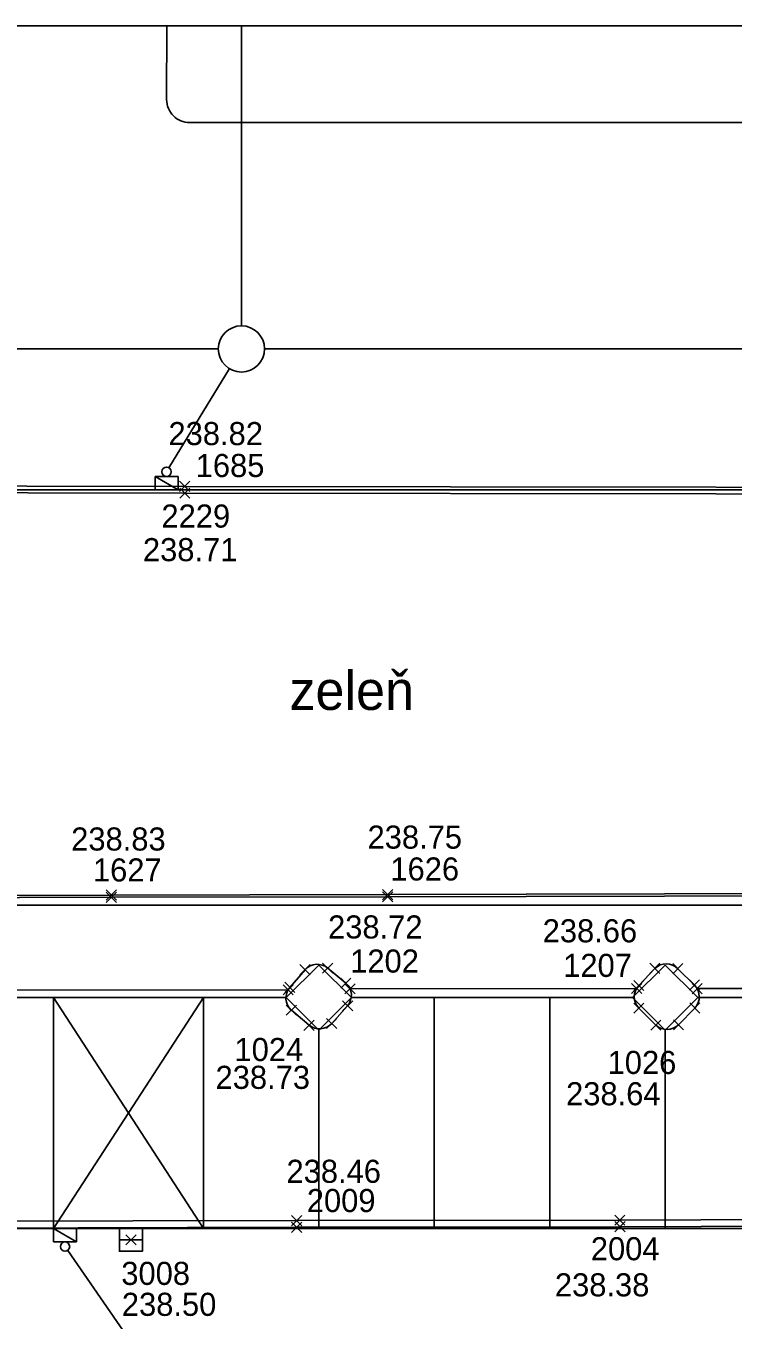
# Model space of a CAD drawing. Extents: x -264165 to -263733, y -1242319 to -1242245.
# Drawn here: x -263956.67 to -263941.36, y -1242272.97 to -1242244.94 of the extents above; entities that cross this region are included whole.
import ezdxf

# ---------------------------------------------------------------- set-up
doc = ezdxf.new("R2010")
doc.units = 0
for name, color, linetype in [('KFA_BOD_CISLO', 7, 'Continuous'), ('KFA_BOD_SYMBOL', 7, 'Continuous'), ('KFA_BOD_VYSKA', 7, 'Continuous'), ('KFA_SO_20-2_OBRUBNIKY_DOLNA_HRANA', 7, 'Continuous'), ('KFA_SO_20-2_OBRUBNIKY_HORNA_HRANA', 7, 'Continuous'), ('KFA_UV_BOD_CISLO', 7, 'Continuous'), ('KFA_UV_BOD_SYMBOL', 7, 'Continuous'), ('KFA_UV_BOD_VYSKA', 7, 'Continuous'), ('POPIS', 7, 'Continuous'), ('PROJEKT_OBRUBNIKY_KOMUNIKACIE', 7, 'Continuous'), ('PROJEKT_TDZ_VODOROVNE', 7, 'Continuous'), ('RAM_NA_TLAC_1-250', 7, 'Continuous'), ('SITUACIA_DSP_2D', 7, 'Continuous'), ('ULICNA_VPUST_POKLOP', 7, 'Continuous')]:
    doc.layers.add(name, color=color, linetype=linetype)

msp = doc.modelspace()

# ---------------------------------------------------------------- linework, layer by layer
at = {"layer": 'KFA_BOD_SYMBOL'}
for p, q in [((-263953.338, -1242255.021), (-263953.117, -1242254.799)), ((-263953.117, -1242255.021), (-263953.338, -1242254.799)), ((-263953.334, -1242255.164), (-263953.113, -1242254.944)), ((-263953.113, -1242255.164), (-263953.334, -1242254.944)), ((-263954.927, -1242263.87), (-263954.705, -1242263.649)), ((-263954.705, -1242263.87), (-263954.927, -1242263.649)), ((-263954.927, -1242263.92), (-263954.705, -1242263.698)), ((-263954.705, -1242263.92), (-263954.927, -1242263.698)), ((-263948.943, -1242263.86), (-263948.721, -1242263.639)), ((-263948.721, -1242263.86), (-263948.943, -1242263.639)), ((-263948.943, -1242263.91), (-263948.721, -1242263.688)), ((-263948.721, -1242263.91), (-263948.943, -1242263.688)), ((-263950.734, -1242265.487), (-263950.513, -1242265.265)), ((-263950.513, -1242265.487), (-263950.734, -1242265.265)), ((-263950.242, -1242265.454), (-263950.02, -1242265.232)), ((-263950.02, -1242265.454), (-263950.242, -1242265.232)), ((-263943.161, -1242265.458), (-263942.94, -1242265.238)), ((-263942.94, -1242265.458), (-263943.161, -1242265.238)), ((-263942.663, -1242265.465), (-263942.442, -1242265.245)), ((-263942.442, -1242265.465), (-263942.663, -1242265.245)), ((-263951.099, -1242265.923), (-263950.878, -1242265.701)), ((-263950.878, -1242265.923), (-263951.099, -1242265.701)), ((-263951.062, -1242265.872), (-263950.84, -1242265.65)), ((-263950.84, -1242265.872), (-263951.062, -1242265.65)), ((-263949.85, -1242265.779), (-263949.628, -1242265.558)), ((-263949.628, -1242265.779), (-263949.85, -1242265.558)), ((-263949.759, -1242265.901), (-263949.538, -1242265.681)), ((-263949.538, -1242265.901), (-263949.759, -1242265.681)), ((-263943.555, -1242265.894), (-263943.334, -1242265.674)), ((-263943.334, -1242265.894), (-263943.555, -1242265.674)), ((-263943.506, -1242265.83), (-263943.285, -1242265.61)), ((-263943.285, -1242265.83), (-263943.506, -1242265.61)), ((-263942.302, -1242265.819), (-263942.081, -1242265.599)), ((-263942.081, -1242265.819), (-263942.302, -1242265.599)), ((-263942.243, -1242265.897), (-263942.022, -1242265.677)), ((-263942.022, -1242265.897), (-263942.243, -1242265.677)), ((-263949.812, -1242266.269), (-263949.59, -1242266.048)), ((-263949.59, -1242266.269), (-263949.812, -1242266.048)), ((-263951.03, -1242266.365), (-263950.808, -1242266.144)), ((-263950.808, -1242266.365), (-263951.03, -1242266.144)), ((-263943.507, -1242266.32), (-263943.285, -1242266.1)), ((-263943.285, -1242266.32), (-263943.507, -1242266.1)), ((-263942.295, -1242266.318), (-263942.073, -1242266.096)), ((-263942.073, -1242266.318), (-263942.295, -1242266.096)), ((-263950.647, -1242266.69), (-263950.426, -1242266.468)), ((-263950.426, -1242266.69), (-263950.647, -1242266.468)), ((-263950.155, -1242266.65), (-263949.933, -1242266.43)), ((-263949.933, -1242266.65), (-263950.155, -1242266.43)), ((-263943.139, -1242266.688), (-263942.917, -1242266.467)), ((-263942.917, -1242266.688), (-263943.139, -1242266.467)), ((-263942.649, -1242266.681), (-263942.428, -1242266.46)), ((-263942.428, -1242266.681), (-263942.649, -1242266.46)), ((-263950.916, -1242270.921), (-263950.695, -1242270.701)), ((-263950.695, -1242270.921), (-263950.916, -1242270.701)), ((-263943.919, -1242270.911), (-263943.698, -1242270.691)), ((-263943.698, -1242270.911), (-263943.919, -1242270.691)), ((-263950.915, -1242271.066), (-263950.693, -1242270.846)), ((-263950.693, -1242271.066), (-263950.915, -1242270.846)), ((-263943.914, -1242271.055), (-263943.693, -1242270.833)), ((-263943.693, -1242271.055), (-263943.914, -1242270.833))]:
    msp.add_line(p, q, dxfattribs=at)
at = {"layer": 'KFA_SO_20-2_OBRUBNIKY_DOLNA_HRANA'}
for points in [[(-263970.225, -1242255.029), (-263963.43, -1242255.035), (-263953.224, -1242255.054), (-263930.231, -1242255.088)], [(-263965.289, -1242270.846), (-263957.9, -1242270.825), (-263950.806, -1242270.811), (-263943.808, -1242270.801), (-263936.795, -1242270.772), (-263929.578, -1242270.752)], [(-263965.143, -1242270.987), (-263957.899, -1242270.977), (-263950.804, -1242270.956), (-263943.803, -1242270.944), (-263936.794, -1242270.917), (-263929.31, -1242270.895)]]:
    msp.add_lwpolyline(points, dxfattribs=at)
at = {"layer": 'KFA_SO_20-2_OBRUBNIKY_HORNA_HRANA'}
for p, q in [((-263950.951, -1242265.761), (-263950.623, -1242265.376)), ((-263950.131, -1242265.343), (-263949.739, -1242265.668)), ((-263943.395, -1242265.72), (-263943.051, -1242265.348)), ((-263942.552, -1242265.355), (-263942.192, -1242265.709)), ((-263942.133, -1242265.787), (-263935.922, -1242265.777)), ((-263957.867, -1242265.823), (-263950.988, -1242265.812)), ((-263949.649, -1242265.791), (-263943.444, -1242265.784)), ((-263950.919, -1242266.254), (-263950.536, -1242266.579)), ((-263949.701, -1242266.158), (-263950.044, -1242266.54)), ((-263943.396, -1242266.21), (-263943.028, -1242266.577)), ((-263942.184, -1242266.207), (-263942.539, -1242266.57))]:
    msp.add_line(p, q, dxfattribs=at)
for points in [[(-263970.225, -1242254.882), (-263963.483, -1242254.892), (-263953.227, -1242254.91), (-263930.229, -1242254.938)], [(-263927.032, -1242263.694), (-263929.858, -1242263.715), (-263931.859, -1242263.708), (-263939.843, -1242263.726), (-263948.832, -1242263.749), (-263954.816, -1242263.759), (-263960.791, -1242263.777), (-263965.254, -1242263.802), (-263965.276, -1242265.854)], [(-263927.18, -1242263.745), (-263929.889, -1242263.765), (-263931.859, -1242263.758), (-263939.843, -1242263.776), (-263948.832, -1242263.799), (-263954.816, -1242263.809), (-263960.791, -1242263.827), (-263965.205, -1242263.852), (-263965.226, -1242265.854)]]:
    msp.add_lwpolyline(points, dxfattribs=at)
for centre, major_axis, ratio, start_param, end_param in [((-263942.805, -1242265.603), (-0.334, -0.118), 0.999583, 3.576129, 5.140228), ((-263950.36, -1242265.609), (-0.344, -0.07), 0.999884, 3.79973, 5.357438), ((-263950.685, -1242265.991), (0.002, -0.352), 0.999397, 3.992341, 5.549094), ((-263949.97, -1242265.932), (0.325, 0.133), 0.999614, 5.197714, 6.746788), ((-263943.139, -1242265.965), (-0.087, -0.344), 0.999684, 4.196564, 5.720294), ((-263942.444, -1242265.962), (0.191, 0.302), 0.999031, 4.520332, 6.062322), ((-263950.31, -1242266.304), (0.29, 0.205), 0.999717, 3.4083, 4.942889), ((-263942.787, -1242266.319), (0.155, 0.317), 0.999622, 2.843241, 4.374597)]:
    msp.add_ellipse(centre, major_axis=major_axis, ratio=ratio, start_param=start_param, end_param=end_param, dxfattribs=at)
at = {"layer": 'KFA_UV_BOD_SYMBOL'}
for p, q in [((-263954.503, -1242271.336), (-263954.281, -1242271.116)), ((-263954.281, -1242271.336), (-263954.503, -1242271.116))]:
    msp.add_line(p, q, dxfattribs=at)
at = {"layer": 'PROJEKT_OBRUBNIKY_KOMUNIKACIE'}
for p, q in [((-263953.618, -1242244.935), (-263953.619, -1242246.529)), ((-263953.119, -1242247.03), (-263930.082, -1242247.03)), ((-263957.861, -1242265.982), (-263951.031, -1242265.982)), ((-263949.617, -1242265.982), (-263943.531, -1242265.982)), ((-263942.117, -1242265.982), (-263936.031, -1242265.982)), ((-263965.568, -1242270.982), (-263929.061, -1242270.982))]:
    msp.add_line(p, q, dxfattribs=at)
for points in [[(-263929.58, -1242254.982), (-263970.077, -1242254.982), (-263970.077, -1242263.982), (-263929.58, -1242263.982), (-263929.58, -1242254.982)], [(-263950.324, -1242265.275), (-263949.617, -1242265.982), (-263950.324, -1242266.689), (-263951.031, -1242265.982), (-263950.324, -1242265.275)], [(-263942.824, -1242265.275), (-263942.117, -1242265.982), (-263942.824, -1242266.689), (-263943.531, -1242265.982), (-263942.824, -1242265.275)]]:
    msp.add_lwpolyline(points, dxfattribs=at)
msp.add_arc((-263953.119, -1242246.53), 0.5, 179.9525, 270, dxfattribs=at)
at = {"layer": 'PROJEKT_TDZ_VODOROVNE'}
for p, q in [((-263956.068, -1242265.982), (-263956.068, -1242270.982)), ((-263956.068, -1242270.982), (-263952.824, -1242265.982)), ((-263956.068, -1242265.982), (-263952.824, -1242270.982)), ((-263952.824, -1242265.982), (-263952.824, -1242270.982)), ((-263947.824, -1242265.982), (-263947.824, -1242270.982)), ((-263945.324, -1242265.982), (-263945.324, -1242270.982)), ((-263950.324, -1242266.689), (-263950.324, -1242270.982)), ((-263942.824, -1242266.689), (-263942.824, -1242270.982))]:
    msp.add_line(p, q, dxfattribs=at)
at = {"layer": 'RAM_NA_TLAC_1-250'}
msp.add_lwpolyline([(-264165.363, -1242244.935), (-263732.863, -1242244.935), (-263732.863, -1242319.185), (-264165.363, -1242319.185)], close=True, dxfattribs=at)
at = {"layer": 'SITUACIA_DSP_2D'}
for p, q in [((-263953.618, -1242244.935), (-263953.619, -1242246.529)), ((-263952, -1242251.432), (-263952, -1242244.935)), ((-263953.119, -1242247.03), (-263930.082, -1242247.03)), ((-263958.575, -1242251.932), (-263952.5, -1242251.932)), ((-263940.302, -1242251.932), (-263951.5, -1242251.932)), ((-263953.57, -1242254.506), (-263952.26, -1242252.359)), ((-263953.87, -1242254.692), (-263953.37, -1242254.692)), ((-263953.87, -1242254.982), (-263953.87, -1242254.692)), ((-263953.87, -1242254.692), (-263953.37, -1242254.982)), ((-263953.87, -1242254.692), (-263953.37, -1242254.982)), ((-263953.37, -1242254.692), (-263953.87, -1242254.692)), ((-263953.37, -1242254.692), (-263953.37, -1242254.982)), ((-263953.37, -1242254.982), (-263953.37, -1242254.692)), ((-263953.37, -1242254.982), (-263953.87, -1242254.982)), ((-263956.068, -1242270.982), (-263955.568, -1242270.982)), ((-263956.068, -1242271.272), (-263956.068, -1242270.982)), ((-263956.068, -1242270.982), (-263955.568, -1242271.272)), ((-263956.068, -1242270.982), (-263955.568, -1242271.272)), ((-263955.568, -1242270.982), (-263956.068, -1242270.982)), ((-263955.568, -1242270.982), (-263955.568, -1242271.272)), ((-263955.568, -1242271.272), (-263955.568, -1242270.982)), ((-263955.568, -1242271.272), (-263956.068, -1242271.272)), ((-263955.761, -1242271.455), (-263947.392, -1242283.571))]:
    msp.add_line(p, q, dxfattribs=at)
msp.add_lwpolyline([(-263929.58, -1242254.982), (-263970.077, -1242254.982), (-263970.077, -1242263.982), (-263929.58, -1242263.982), (-263929.58, -1242254.982)], dxfattribs=at)
for points in [[(-263950.324, -1242265.275), (-263949.617, -1242265.982), (-263950.324, -1242266.689), (-263951.031, -1242265.982)], [(-263942.824, -1242265.275), (-263942.117, -1242265.982), (-263942.824, -1242266.689), (-263943.531, -1242265.982)]]:
    msp.add_lwpolyline(points, close=True, dxfattribs=at)
for centre, radius in [((-263952, -1242251.932), 0.5), ((-263953.62, -1242254.592), 0.1), ((-263955.818, -1242271.373), 0.1)]:
    msp.add_circle(centre, radius, dxfattribs=at)
msp.add_arc((-263953.119, -1242246.53), 0.5, 179.9525, 270, dxfattribs=at)
at = {"layer": 'ULICNA_VPUST_POKLOP'}
msp.add_line((-263954.392, -1242271.226), (-263954.392, -1242271.226), dxfattribs=at)
msp.add_lwpolyline([(-263954.642, -1242271.226), (-263954.642, -1242270.976), (-263954.142, -1242270.976), (-263954.142, -1242271.476), (-263954.642, -1242271.476), (-263954.642, -1242271.226), (-263954.142, -1242271.226)], dxfattribs=at)

# ---------------------------------------------------------------- texts
at = {"layer": 'KFA_BOD_CISLO'}
for s, p in [('1685', (-263952.989, -1242254.706)), ('2229', (-263953.731, -1242255.801)), ('1627', (-263955.214, -1242263.466)), ('1626', (-263948.775, -1242263.445)), ('1202', (-263949.645, -1242265.439)), ('1207', (-263945.034, -1242265.533)), ('1024', (-263952.15, -1242267.355)), ('1026', (-263944.072, -1242267.635)), ('2009', (-263950.584, -1242270.626)), ('2004', (-263944.435, -1242271.67))]:
    msp.add_text(s, height=0.5, dxfattribs=at).set_placement(p)
at = {"layer": 'KFA_BOD_VYSKA'}
for s, p in [('238.82', (-263953.579, -1242254.015)), ('238.71', (-263954.132, -1242256.529)), ('238.83', (-263955.685, -1242262.796)), ('238.75', (-263949.269, -1242262.755)), ('238.72', (-263950.124, -1242264.701)), ('238.66', (-263945.478, -1242264.784)), ('238.73', (-263952.56, -1242267.958)), ('238.64', (-263944.971, -1242268.313)), ('238.46', (-263951.024, -1242269.993)), ('238.38', (-263945.213, -1242272.452))]:
    msp.add_text(s, height=0.5, dxfattribs=at).set_placement(p)
at = {"layer": 'KFA_UV_BOD_CISLO'}
msp.add_text('3008', height=0.5, dxfattribs=at).set_placement((-263954.6, -1242272.204))
at = {"layer": 'KFA_UV_BOD_VYSKA'}
msp.add_text('238.50', height=0.5, dxfattribs=at).set_placement((-263954.588, -1242272.874))
at = {"layer": 'POPIS'}
msp.add_text('zeleň', height=0.8438, dxfattribs=at).set_placement((-263950.961, -1242259.75))

doc.saveas('drawing.dxf')
